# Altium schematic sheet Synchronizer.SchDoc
size A4; DocumentNumber: 5; SheetNumber: 5; SheetTotal: 5
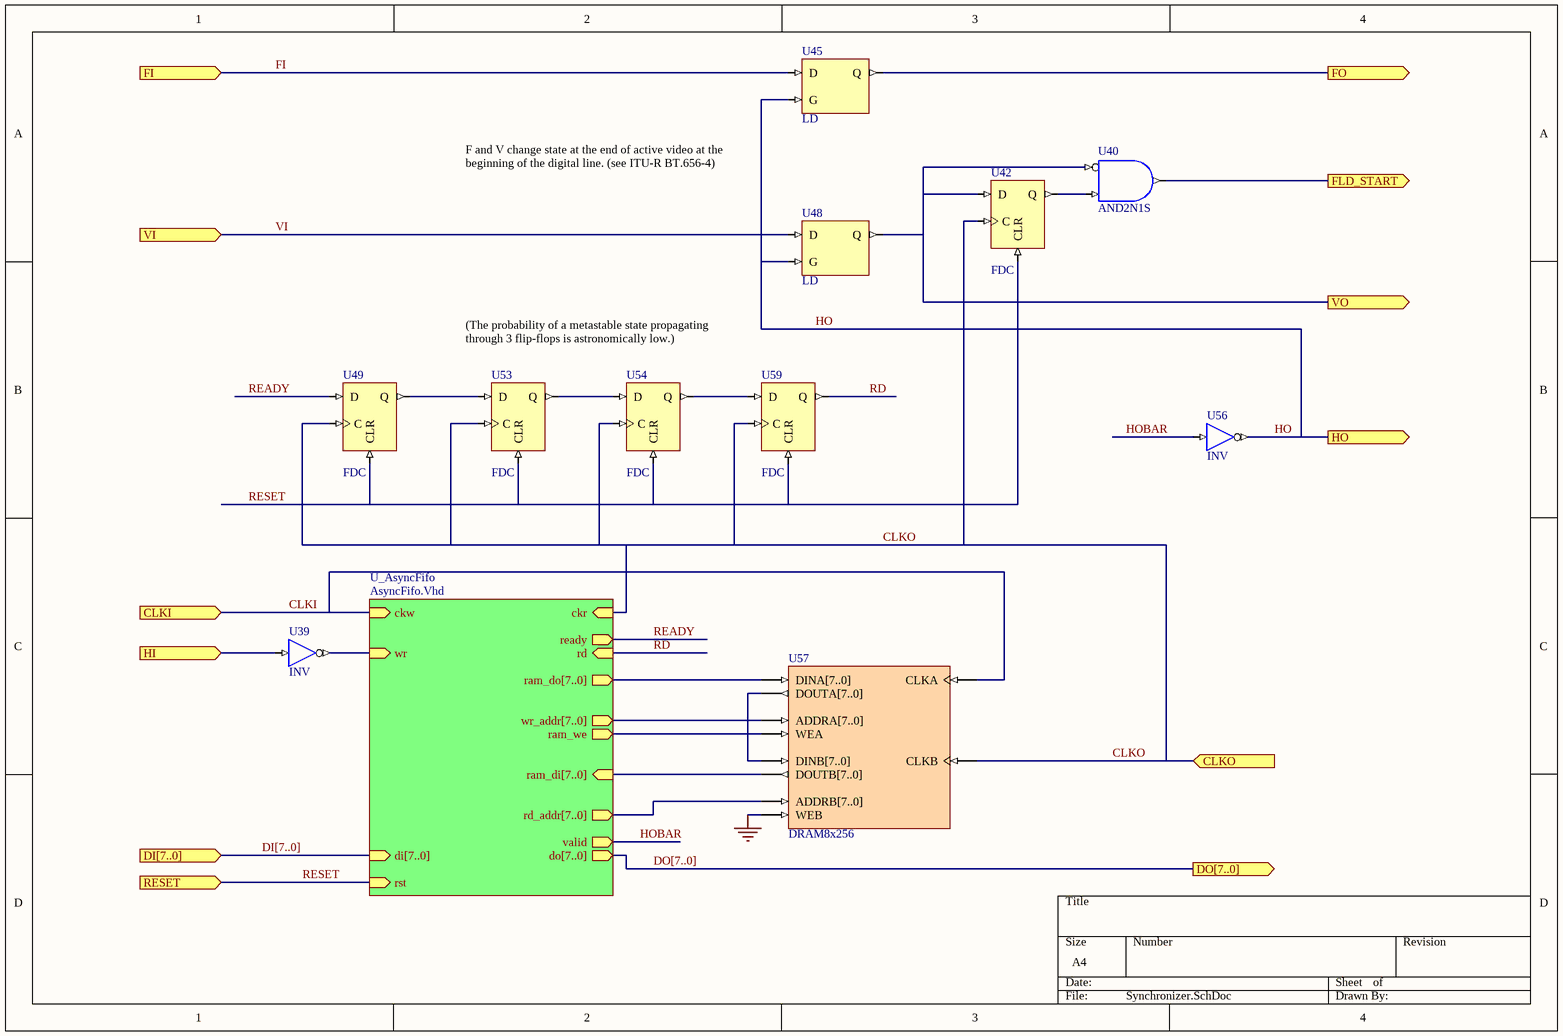
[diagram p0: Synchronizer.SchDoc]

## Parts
U39  INV
U40  AND2N1S
U42  FDC
U45  LD
U48  LD
U49  FDC
U53  FDC
U54  FDC
U56  INV
U57  DRAM8x256
U59  FDC

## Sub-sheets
U_AsyncFifo = AsyncFifo.Vhd: ckr (in), ckw (in), di[7..0] (in), do[7..0] (out), ram_di[7..0] (in), ram_do[7..0] (out), ram_we (out), rd (in), rd_addr[7..0] (out), ready (out), rst (in), valid (out), wr (in), wr_addr[7..0] (out)  | VHDLENTITY: AsyncFifo

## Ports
CLKI (in), CLKO (in), DI[7..0] (in), DO[7..0] (out), FI (in), FLD_START (out), FO (out), HI (in), HO (out), RESET (in), VI (in), VO (out)

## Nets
GND: U57.WEB
CLKI: U57.CLKA ; port CLKI, sheet U_AsyncFifo/ckw
CLKO: U42.C U49.C U53.C U54.C U57.CLKB U59.C ; port CLKO, sheet U_AsyncFifo/ckr
FI: U45.D ; port FI
FLD_START: U40.O ; port FLD_START
FO: U45.Q ; port FO
HI: U39.I ; port HI
HO: U45.G U48.G U56.O ; port HO
HOBAR: U56.I ; sheet U_AsyncFifo/valid
RD: U59.Q ; sheet U_AsyncFifo/rd
READY: U49.D ; sheet U_AsyncFifo/ready
RESET: U42.CLR U49.CLR U53.CLR U54.CLR U59.CLR ; port RESET, sheet U_AsyncFifo/rst
VI: U48.D ; port VI
VO: U40.I0 U42.D U48.Q ; port VO
NetU39_O: U39.O ; sheet U_AsyncFifo/wr
NetU40_I1: U40.I1 U42.Q
NetU49_Q: U49.Q U53.D
NetU53_Q: U53.Q U54.D
NetU54_Q: U54.Q U59.D
NetU57_WEA: U57.WEA ; sheet U_AsyncFifo/ram_we

Not connected (* = marked no-connect by the designer): U57 ADDRA[7..0] ADDRB[7..0] DINA[7..0] DINB[7..0] DOUTA[7..0] DOUTB[7..0]

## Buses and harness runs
bus DI[7..0] = port DI[7..0] = sheet U_AsyncFifo/di[7..0]
bus DO[7..0] = port DO[7..0] = sheet U_AsyncFifo/do[7..0]

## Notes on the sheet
- F and V change state at the end of active video at the beginning of the digital line. (see ITU-R BT.656-4)
- (The probability of a metastable state propagating through 3 flip-flops is astronomically low.)

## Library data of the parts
U39 U56 = INV: Inverter; ArchiveName: GENERIC
U40 = AND2N1S: 2-Input AND Gate with Active Low A Input, Single Pin Version; Xilinx Equivalent: AND2B1; ArchiveName: GENERIC
U42 U49 U53 U54 U59 = FDC: D-Type Flip-Flop with Asynchronous Clear; ArchiveName: GENERIC
U45 U48 = LD: Transparent Data Latch; ArchiveName: GENERIC
U57 = DRAM8x256: Dual Port Random Access Memory 256 x 8 and 256 x 8; Memory_DepthA: 256; Memory_Type: RAM_DualPortBlock; Memory_WidthA: 8; Memory_ClockEdge: Rising; Nexus_Core: Memory_Program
